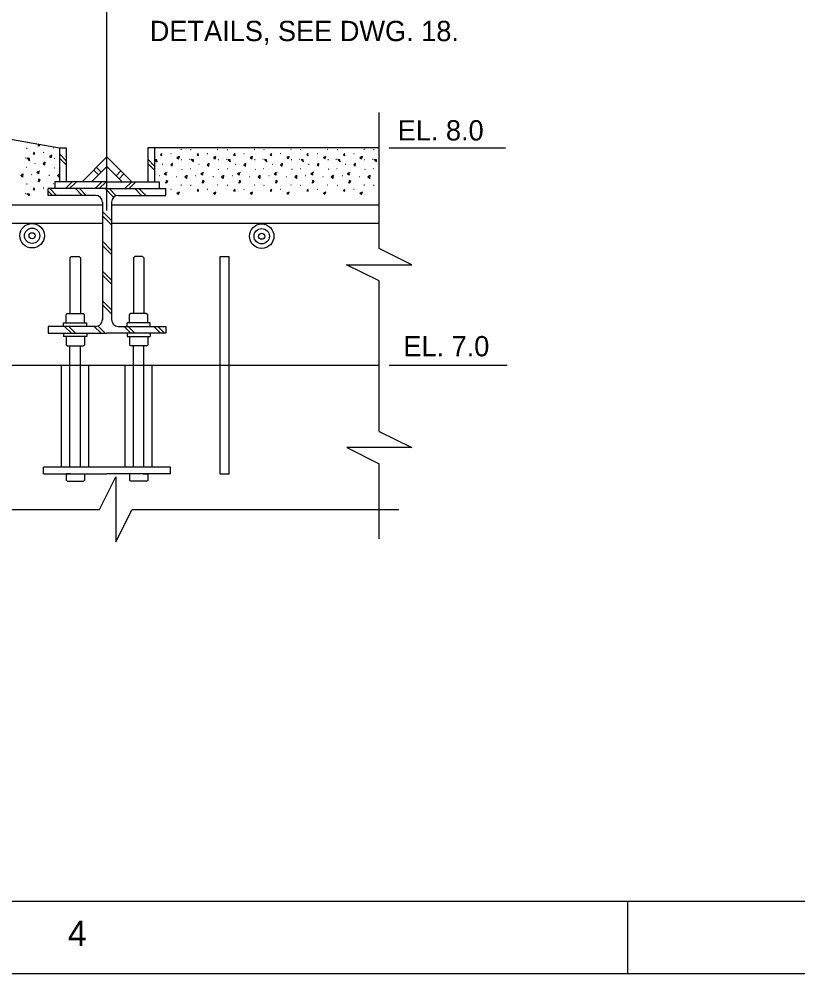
# Model space of a CAD drawing. Extents: x 0 to 320, y -4 to 473.
# Drawn here: x 12.43 to 17.8, y 0 to 6.59 of the extents above; entities that cross this region are included whole.
import ezdxf

# ---------------------------------------------------------------- set-up
doc = ezdxf.new("R2010")
doc.units = 0
for name, color, linetype in [('Level 1', 7, 'Continuous'), ('Level 2', 7, 'Continuous'), ('Level 44', 7, 'Continuous'), ('Level 50', 7, 'Continuous')]:
    doc.layers.add(name, color=color, linetype=linetype)

msp = doc.modelspace()

# ---------------------------------------------------------------- linework, layer by layer
at = {"layer": 'Level 1'}
msp.add_line((16.625, 0.5), (16.625, 0), dxfattribs=at)
for points in [[(0, 28), (40, 28), (40, 0), (0, 0)], [(1.5, 27.5), (39.5, 27.5), (39.5, 0.5), (1.5, 0.5)]]:
    msp.add_lwpolyline(points, close=True, dxfattribs=at)
at = {"layer": 'Level 2'}
for p, q in [((12.0104, 5.8276), (12.7057, 5.7025)), ((12.7057, 5.7025), (12.7057, 5.4682)), ((12.7057, 5.7025), (12.7526, 5.7025)), ((12.7526, 5.7025), (12.7526, 5.4682)), ((14.9124, 5.7025), (13.3151, 5.7025)), ((13.3151, 5.7025), (13.3151, 5.4682)), ((13.3619, 5.7025), (13.3619, 5.4682)), ((12.7526, 5.6139), (12.7057, 5.6608)), ((12.7526, 5.5856), (12.7057, 5.6325)), ((13.0338, 5.64), (12.8619, 5.4682)), ((13.0338, 5.64), (13.2057, 5.4682)), ((13.3619, 5.577), (13.3151, 5.6238)), ((13.0338, 5.5738), (12.9282, 5.4682)), ((12.9759, 5.5159), (12.9428, 5.549)), ((12.9949, 5.5348), (12.9618, 5.568)), ((13.0338, 5.5738), (13.1394, 5.4682)), ((13.0971, 5.5104), (13.1303, 5.5436)), ((13.3619, 5.5487), (13.3151, 5.5956)), ((13.1174, 5.4902), (13.1505, 5.5233)), ((13.0338, 5.4213), (12.6276, 5.4213)), ((12.6276, 5.3744), (12.6276, 5.4213)), ((12.6859, 5.3744), (12.639, 5.4213)), ((13.0338, 5.4682), (12.6744, 5.4682)), ((12.6744, 5.4682), (12.6744, 5.4213)), ((12.7476, 5.4213), (12.7945, 5.4682)), ((12.7759, 5.4213), (12.8227, 5.4682)), ((12.8627, 5.3744), (12.8158, 5.4213)), ((12.8909, 5.3744), (12.8441, 5.4213)), ((12.9526, 5.4213), (12.9995, 5.4682)), ((12.9809, 5.4213), (13.0278, 5.4682)), ((13.0801, 5.362), (13.0209, 5.4213)), ((13.0338, 5.4682), (13.3932, 5.4682)), ((13.0338, 5.4213), (13.4401, 5.4213)), ((13.0981, 5.3723), (13.0491, 5.4213)), ((13.1577, 5.4213), (13.2046, 5.4682)), ((13.186, 5.4213), (13.2329, 5.4682)), ((13.2728, 5.3744), (13.2259, 5.4213)), ((13.3011, 5.3744), (13.2542, 5.4213)), ((13.3932, 5.4682), (13.3932, 5.4213)), ((13.4401, 5.3744), (13.4401, 5.4213)), ((12.6576, 5.3744), (12.6276, 5.4045)), ((12.9557, 5.3744), (12.6276, 5.3744)), ((13.1119, 5.3744), (13.4401, 5.3744)), ((13.0026, 5.3068), (11.4791, 5.3068)), ((13.0026, 5.3275), (13.0026, 4.5135)), ((13.0651, 5.3275), (13.0651, 4.5135)), ((14.9124, 5.3068), (13.0651, 5.3068)), ((13.0651, 5.2003), (13.0026, 5.2628)), ((13.0651, 5.172), (13.0026, 5.2345)), ((13.0026, 5.1818), (11.4791, 5.1818)), ((14.9124, 5.1818), (13.0651, 5.1818)), ((13.0651, 4.9953), (13.0026, 5.0578)), ((13.0651, 4.967), (13.0026, 5.0295)), ((12.7785, 4.9434), (12.7876, 4.9525)), ((12.7876, 4.9525), (12.8421, 4.9525)), ((12.8512, 4.9434), (12.8421, 4.9525)), ((13.2164, 4.9434), (13.2255, 4.9525)), ((13.28, 4.9525), (13.2255, 4.9525)), ((13.2891, 4.9434), (13.28, 4.9525)), ((13.8151, 3.4525), (13.8151, 4.9525)), ((13.8776, 3.4525), (13.8776, 4.9525)), ((12.7787, 4.9434), (12.7787, 4.5583)), ((12.8514, 4.9434), (12.8514, 4.5583)), ((13.2162, 4.9434), (13.2162, 4.5583)), ((13.2889, 4.9434), (13.2889, 4.5583)), ((13.0651, 4.7902), (13.0026, 4.8527)), ((13.0651, 4.7619), (13.0026, 4.8244)), ((13.0651, 4.5851), (13.0026, 4.6476)), ((13.0651, 4.5568), (13.0026, 4.6193)), ((12.7607, 4.5583), (12.7523, 4.5534)), ((12.7523, 4.4938), (12.7523, 4.5534)), ((12.7607, 4.5583), (12.8694, 4.5583)), ((12.8694, 4.5583), (12.8779, 4.5534)), ((12.8779, 4.4938), (12.8779, 4.5534)), ((13.1982, 4.5583), (13.1898, 4.5534)), ((13.1898, 4.4938), (13.1898, 4.5534)), ((13.3069, 4.5583), (13.1982, 4.5583)), ((13.3069, 4.5583), (13.3154, 4.5534)), ((13.3154, 4.4938), (13.3154, 4.5534)), ((12.7348, 4.4938), (12.8954, 4.4938)), ((12.7348, 4.4703), (12.7348, 4.4938)), ((12.7787, 4.4915), (12.7787, 4.4938)), ((12.8514, 4.4915), (12.8514, 4.4938)), ((12.8954, 4.4703), (12.8954, 4.4938)), ((13.3329, 4.4938), (13.1723, 4.4938)), ((13.1723, 4.4703), (13.1723, 4.4938)), ((13.2162, 4.4915), (13.2162, 4.4938)), ((13.2889, 4.4915), (13.2889, 4.4938)), ((13.3329, 4.4703), (13.3329, 4.4938)), ((12.9557, 4.4703), (12.6276, 4.4703)), ((12.6276, 4.4703), (12.6276, 4.4235)), ((12.6276, 4.4235), (13.0338, 4.4235)), ((12.7348, 4.4235), (12.7348, 4.4)), ((12.7883, 4.4235), (12.7414, 4.4703)), ((12.8166, 4.4235), (12.7697, 4.4703)), ((12.8954, 4.4235), (12.8954, 4.4)), ((12.9934, 4.4235), (12.9465, 4.4703)), ((13.0216, 4.4235), (12.9719, 4.4732)), ((13.4401, 4.4235), (13.0338, 4.4235)), ((13.1119, 4.4703), (13.4401, 4.4703)), ((13.1984, 4.4235), (13.1516, 4.4703)), ((13.1723, 4.4235), (13.1723, 4.4)), ((13.2267, 4.4235), (13.1798, 4.4703)), ((13.3329, 4.4235), (13.3329, 4.4)), ((13.4035, 4.4235), (13.3566, 4.4703)), ((13.4318, 4.4235), (13.3849, 4.4703)), ((13.4401, 4.4703), (13.4401, 4.4235)), ((12.8954, 4.4), (12.7348, 4.4)), ((12.7523, 4.4), (12.7523, 4.3404)), ((12.7787, 4.4023), (12.7787, 4.4)), ((12.8514, 4.4023), (12.8514, 4.4)), ((12.8779, 4.4), (12.8779, 4.3404)), ((13.1723, 4.4), (13.3329, 4.4)), ((13.1898, 4.4), (13.1898, 4.3404)), ((13.2162, 4.4023), (13.2162, 4.4)), ((13.2889, 4.4023), (13.2889, 4.4)), ((13.3154, 4.4), (13.3154, 4.3404)), ((12.7607, 4.3355), (12.7523, 4.3404)), ((12.7607, 4.3355), (12.8694, 4.3355)), ((12.7787, 3.4994), (12.7787, 4.3355)), ((12.8514, 3.4994), (12.8514, 4.3355)), ((12.8694, 4.3355), (12.8779, 4.3404)), ((13.1982, 4.3355), (13.1898, 4.3404)), ((13.3069, 4.3355), (13.1982, 4.3355)), ((13.2162, 3.4994), (13.2162, 4.3355)), ((13.2889, 3.4994), (13.2889, 4.3355)), ((13.3069, 4.3355), (13.3154, 4.3404)), ((7.5674, 4.2025), (14.9124, 4.2025)), ((12.7213, 3.4994), (12.7213, 4.2025)), ((12.9088, 3.4994), (12.9088, 4.2025)), ((13.1588, 3.4994), (13.1588, 4.2025)), ((13.3463, 3.4994), (13.3463, 4.2025)), ((12.5963, 3.4525), (12.5963, 3.4994)), ((13.0338, 3.4994), (12.5963, 3.4994)), ((13.4713, 3.4994), (13.0338, 3.4994)), ((13.4713, 3.4525), (13.4713, 3.4994)), ((12.5963, 3.4525), (13.0338, 3.4525)), ((12.7844, 3.4523), (12.7526, 3.4523)), ((12.7526, 3.4523), (12.7526, 3.4063)), ((12.779, 3.4546), (12.779, 3.4523)), ((12.8518, 3.4546), (12.8518, 3.4523)), ((12.8782, 3.4523), (12.8782, 3.4063)), ((13.4713, 3.4525), (13.0338, 3.4525)), ((13.1894, 3.4523), (13.1894, 3.4063)), ((13.2158, 3.4546), (13.2158, 3.4523)), ((13.2832, 3.4523), (13.315, 3.4523)), ((13.2886, 3.4546), (13.2886, 3.4523)), ((13.315, 3.4523), (13.315, 3.4063)), ((12.761, 3.4014), (12.7526, 3.4063)), ((12.761, 3.4014), (12.8698, 3.4014)), ((12.8698, 3.4014), (12.8782, 3.4063)), ((13.1978, 3.4014), (13.1894, 3.4063)), ((13.3066, 3.4014), (13.1978, 3.4014)), ((13.3066, 3.4014), (13.315, 3.4063))]:
    msp.add_line(p, q, dxfattribs=at)
for centre, start, end in [((12.9557, 5.3275), 0.00001, 90), ((13.1119, 5.3275), 90, 179.99999), ((12.9557, 4.5172), 269.99999, 359.99999), ((13.1119, 4.5172), 180.00001, 270)]:
    msp.add_arc(centre, 0.0469, start, end, dxfattribs=at)
at = {"layer": 'Level 44'}
for p, q in [((14.9124, 5.0084), (14.9124, 5.9461)), ((12.4828, 5.6984), (12.4794, 5.6984)), ((12.5597, 5.7152), (12.5572, 5.7154)), ((12.5973, 5.6711), (12.5943, 5.6696)), ((12.6681, 5.7005), (12.6656, 5.701)), ((13.5471, 5.6918), (13.5446, 5.6923)), ((13.6144, 5.6897), (13.611, 5.6897)), ((13.7996, 5.6918), (13.7971, 5.6923)), ((13.8669, 5.6897), (13.8635, 5.6897)), ((14.0521, 5.6918), (14.0496, 5.6923)), ((14.1194, 5.6897), (14.116, 5.6897)), ((14.3046, 5.6918), (14.3021, 5.6923)), ((14.3719, 5.6897), (14.3685, 5.6897)), ((14.5571, 5.6918), (14.5546, 5.6923)), ((14.6244, 5.6897), (14.621, 5.6897)), ((14.8096, 5.6918), (14.8071, 5.6923)), ((14.8769, 5.6897), (14.8735, 5.6897)), ((14.9812, 5.7025), (15.7839, 5.7025)), ((12.4756, 5.6308), (12.4724, 5.6308)), ((12.6721, 5.6296), (12.6687, 5.6296)), ((13.4764, 5.6624), (13.4734, 5.6609)), ((13.5511, 5.6209), (13.5477, 5.6209)), ((13.6071, 5.6221), (13.6039, 5.6221)), ((13.7289, 5.6624), (13.7259, 5.6609)), ((13.8036, 5.6209), (13.8002, 5.6209)), ((13.8596, 5.6221), (13.8564, 5.6221)), ((13.9814, 5.6624), (13.9784, 5.6609)), ((14.0561, 5.6209), (14.0527, 5.6209)), ((14.1121, 5.6221), (14.1089, 5.6221)), ((14.2339, 5.6624), (14.2309, 5.6609)), ((14.3086, 5.6209), (14.3052, 5.6209)), ((14.3646, 5.6221), (14.3614, 5.6221)), ((14.4864, 5.6624), (14.4834, 5.6609)), ((14.5611, 5.6209), (14.5577, 5.6209)), ((14.6171, 5.6221), (14.6139, 5.6221)), ((14.7389, 5.6624), (14.7359, 5.6609)), ((14.8136, 5.6209), (14.8102, 5.6209)), ((14.8696, 5.6221), (14.8664, 5.6221)), ((12.4805, 5.5675), (12.4781, 5.5666)), ((12.5392, 5.5959), (12.5359, 5.5964)), ((12.571, 5.541), (12.5682, 5.5427)), ((12.6747, 5.5642), (12.6714, 5.5632)), ((13.4182, 5.5871), (13.415, 5.5877)), ((13.5538, 5.5555), (13.5504, 5.5545)), ((13.612, 5.5588), (13.6096, 5.5579)), ((13.6707, 5.5871), (13.6675, 5.5877)), ((13.8063, 5.5555), (13.8029, 5.5545)), ((13.8645, 5.5588), (13.8621, 5.5579)), ((13.9232, 5.5871), (13.92, 5.5877)), ((14.0588, 5.5555), (14.0554, 5.5545)), ((14.117, 5.5588), (14.1146, 5.5579)), ((14.1757, 5.5871), (14.1725, 5.5877)), ((14.3113, 5.5555), (14.3079, 5.5545)), ((14.3695, 5.5588), (14.3671, 5.5579)), ((14.4282, 5.5871), (14.425, 5.5877)), ((14.5638, 5.5555), (14.5604, 5.5545)), ((14.622, 5.5588), (14.6196, 5.5579)), ((14.6807, 5.5871), (14.6775, 5.5877)), ((14.8163, 5.5555), (14.8129, 5.5545)), ((14.8745, 5.5588), (14.8721, 5.5579)), ((12.5166, 5.5178), (12.5139, 5.519)), ((12.6365, 5.5118), (12.6337, 5.5115)), ((13.3956, 5.5091), (13.3929, 5.5103)), ((13.45, 5.5323), (13.4472, 5.534)), ((13.5155, 5.5031), (13.5128, 5.5028)), ((13.6481, 5.5091), (13.6454, 5.5103)), ((13.7025, 5.5323), (13.6997, 5.534)), ((13.768, 5.5031), (13.7653, 5.5028)), ((13.9006, 5.5091), (13.8979, 5.5103)), ((13.955, 5.5323), (13.9522, 5.534)), ((14.0205, 5.5031), (14.0178, 5.5028)), ((14.1531, 5.5091), (14.1504, 5.5103)), ((14.2075, 5.5323), (14.2047, 5.534)), ((14.273, 5.5031), (14.2703, 5.5028)), ((14.4056, 5.5091), (14.4029, 5.5103)), ((14.46, 5.5323), (14.4572, 5.534)), ((14.5255, 5.5031), (14.5228, 5.5028)), ((14.6581, 5.5091), (14.6554, 5.5103)), ((14.7125, 5.5323), (14.7097, 5.534)), ((14.778, 5.5031), (14.7753, 5.5028)), ((14.9106, 5.5091), (14.9079, 5.5103)), ((12.4828, 5.4525), (12.4794, 5.4525)), ((12.5597, 5.4692), (12.5572, 5.4694)), ((12.5973, 5.4252), (12.5943, 5.4237)), ((12.6681, 5.4546), (12.6656, 5.455)), ((13.4388, 5.4605), (13.4363, 5.4607)), ((13.4764, 5.4165), (13.4734, 5.415)), ((13.5471, 5.4459), (13.5446, 5.4463)), ((13.6144, 5.4438), (13.611, 5.4438)), ((13.6913, 5.4605), (13.6888, 5.4607)), ((13.7289, 5.4165), (13.7259, 5.415)), ((13.7996, 5.4459), (13.7971, 5.4463)), ((13.8669, 5.4438), (13.8635, 5.4438)), ((13.9438, 5.4605), (13.9413, 5.4607)), ((13.9814, 5.4165), (13.9784, 5.415)), ((14.0521, 5.4459), (14.0496, 5.4463)), ((14.1194, 5.4438), (14.116, 5.4438)), ((14.1963, 5.4605), (14.1938, 5.4607)), ((14.2339, 5.4165), (14.2309, 5.415)), ((14.3046, 5.4459), (14.3021, 5.4463)), ((14.3719, 5.4438), (14.3685, 5.4438)), ((14.4488, 5.4605), (14.4463, 5.4607)), ((14.4864, 5.4165), (14.4834, 5.415)), ((14.5571, 5.4459), (14.5546, 5.4463)), ((14.6244, 5.4438), (14.621, 5.4438)), ((14.7013, 5.4605), (14.6988, 5.4607)), ((14.7389, 5.4165), (14.7359, 5.415)), ((14.8096, 5.4459), (14.8071, 5.4463)), ((14.8769, 5.4438), (14.8735, 5.4438)), ((12.4756, 5.3849), (12.4724, 5.3849)), ((13.8151, 4.9525), (13.8776, 4.9525)), ((14.9124, 3.7449), (14.9124, 4.7841)), ((14.9812, 4.2025), (15.7937, 4.2025)), ((14.9124, 3.0027), (14.9124, 3.5207)), ((13.8151, 3.4525), (13.8776, 3.4525)), ((10.9819, 3.2068), (12.9835, 3.2068)), ((13.2077, 3.2068), (15.0473, 3.2068))]:
    msp.add_line(p, q, dxfattribs=at)
for points in [[(12.4516, 5.7467), (12.4495, 5.7486)], [(12.4516, 5.7482), (12.4516, 5.7467)], [(12.5624, 5.7283), (12.5634, 5.7143)], [(12.5634, 5.7143), (12.574, 5.7262)], [(13.378, 5.6213), (13.3646, 5.622)], [(13.3646, 5.6205), (13.3793, 5.6055), (13.378, 5.6213)], [(12.499, 5.384), (12.484, 5.3849), (12.4945, 5.3741)], [(12.4998, 5.3741), (12.499, 5.384)]]:
    msp.add_lwpolyline(points, dxfattribs=at)
for points in [[(12.5333, 5.6584), (12.5316, 5.6721), (12.5239, 5.6607)], [(12.499, 5.63), (12.484, 5.6308), (12.5002, 5.6142)], [(12.6074, 5.6049), (12.5946, 5.5937), (12.6052, 5.5847)], [(12.6484, 5.6369), (12.6544, 5.6522), (12.6378, 5.6442)], [(13.4124, 5.6497), (13.4106, 5.6634), (13.4029, 5.652)], [(13.5275, 5.6282), (13.5334, 5.6435), (13.5169, 5.6355)], [(13.6305, 5.6213), (13.6155, 5.6221), (13.6318, 5.6055)], [(13.6649, 5.6497), (13.6631, 5.6634), (13.6554, 5.652)], [(13.78, 5.6282), (13.7859, 5.6435), (13.7694, 5.6355)], [(13.883, 5.6213), (13.868, 5.6221), (13.8843, 5.6055)], [(13.9174, 5.6497), (13.9156, 5.6634), (13.9079, 5.652)], [(14.0325, 5.6282), (14.0384, 5.6435), (14.0219, 5.6355)], [(14.1355, 5.6213), (14.1205, 5.6221), (14.1368, 5.6055)], [(14.1699, 5.6497), (14.1681, 5.6634), (14.1604, 5.652)], [(14.285, 5.6282), (14.2909, 5.6435), (14.2744, 5.6355)], [(14.388, 5.6213), (14.373, 5.6221), (14.3893, 5.6055)], [(14.4224, 5.6497), (14.4206, 5.6634), (14.4129, 5.652)], [(14.5375, 5.6282), (14.5434, 5.6435), (14.5269, 5.6355)], [(14.6405, 5.6213), (14.6255, 5.6221), (14.6418, 5.6055)], [(14.6749, 5.6497), (14.6731, 5.6634), (14.6654, 5.652)], [(14.79, 5.6282), (14.7959, 5.6435), (14.7794, 5.6355)], [(14.893, 5.6213), (14.878, 5.6221), (14.8943, 5.6055)], [(12.5621, 5.5234), (12.5501, 5.5324), (12.5616, 5.5426)], [(13.4865, 5.5961), (13.4737, 5.585), (13.4843, 5.576)], [(13.739, 5.5961), (13.7262, 5.585), (13.7368, 5.576)], [(13.9915, 5.5961), (13.9787, 5.585), (13.9893, 5.576)], [(14.244, 5.5961), (14.2312, 5.585), (14.2418, 5.576)], [(14.4965, 5.5961), (14.4837, 5.585), (14.4943, 5.576)], [(14.749, 5.5961), (14.7362, 5.585), (14.7468, 5.576)], [(12.4516, 5.5008), (12.44, 5.5115), (12.4528, 5.5229)], [(12.5634, 5.4684), (12.5741, 5.4804), (12.5621, 5.4867)], [(12.7041, 5.5008), (12.6925, 5.5115), (12.7053, 5.5229)], [(13.4412, 5.5146), (13.4292, 5.5237), (13.4407, 5.5339)], [(13.4424, 5.4596), (13.4531, 5.4716), (13.4412, 5.478)], [(13.5831, 5.4921), (13.5715, 5.5028), (13.5844, 5.5142)], [(13.6937, 5.5146), (13.6817, 5.5237), (13.6932, 5.5339)], [(13.6949, 5.4596), (13.7056, 5.4716), (13.6937, 5.478)], [(13.8356, 5.4921), (13.824, 5.5028), (13.8369, 5.5142)], [(13.9462, 5.5146), (13.9342, 5.5237), (13.9457, 5.5339)], [(13.9474, 5.4596), (13.9581, 5.4716), (13.9462, 5.478)], [(14.0881, 5.4921), (14.0765, 5.5028), (14.0894, 5.5142)], [(14.1987, 5.5146), (14.1867, 5.5237), (14.1982, 5.5339)], [(14.1999, 5.4596), (14.2106, 5.4716), (14.1987, 5.478)], [(14.3406, 5.4921), (14.329, 5.5028), (14.3419, 5.5142)], [(14.4512, 5.5146), (14.4392, 5.5237), (14.4507, 5.5339)], [(14.4524, 5.4596), (14.4631, 5.4716), (14.4512, 5.478)], [(14.5931, 5.4921), (14.5815, 5.5028), (14.5944, 5.5142)], [(14.7037, 5.5146), (14.6917, 5.5237), (14.7032, 5.5339)], [(14.7049, 5.4596), (14.7156, 5.4716), (14.7037, 5.478)], [(14.8456, 5.4921), (14.834, 5.5028), (14.8469, 5.5142)], [(12.5333, 5.4125), (12.5316, 5.4262), (12.5239, 5.4147)], [(13.6649, 5.4038), (13.6631, 5.4175), (13.6554, 5.406)], [(13.9174, 5.4038), (13.9156, 5.4175), (13.9079, 5.406)], [(14.1699, 5.4038), (14.1681, 5.4175), (14.1604, 5.406)], [(14.4224, 5.4038), (14.4206, 5.4175), (14.4129, 5.406)], [(14.6749, 5.4038), (14.6731, 5.4175), (14.6654, 5.406)], [(13.5275, 5.3823), (13.5334, 5.3976), (13.5169, 5.3895)], [(13.78, 5.3823), (13.7859, 5.3976), (13.7694, 5.3895)], [(14.0325, 5.3823), (14.0384, 5.3976), (14.0219, 5.3895)], [(14.285, 5.3823), (14.2909, 5.3976), (14.2744, 5.3895)], [(14.5375, 5.3823), (14.5434, 5.3976), (14.5269, 5.3895)], [(14.79, 5.3823), (14.7959, 5.3976), (14.7794, 5.3895)]]:
    msp.add_lwpolyline(points, close=True, dxfattribs=at)
at = {"layer": 'Level 50'}
for p, q in [((13.0338, 5.2705), (13.0338, 7.4143)), ((15.1369, 4.8959), (14.9124, 5.0084)), ((14.9124, 4.7841), (14.6874, 4.8959)), ((14.6874, 4.8959), (15.1369, 4.8959)), ((14.9124, 3.7449), (15.1374, 3.6332)), ((15.1374, 3.6332), (14.6879, 3.6332)), ((14.6879, 3.6332), (14.9124, 3.5207)), ((12.9835, 3.2068), (13.0952, 3.4318)), ((13.0952, 3.4318), (13.0952, 2.9823)), ((13.0952, 2.9823), (13.2077, 3.2068))]:
    msp.add_line(p, q, dxfattribs=at)
for centre, radius in [((12.5177, 5.0961), 0.0844), ((12.5177, 5.0961), 0.0527), ((14.1014, 5.0931), 0.0844), ((14.1014, 5.0931), 0.0527), ((12.5177, 5.0961), 0.0211), ((14.1014, 5.0931), 0.0211)]:
    msp.add_circle(centre, radius, dxfattribs=at)

# ---------------------------------------------------------------- texts
at = {"layer": 'Level 1'}
msp.add_text('4', height=0.1753, dxfattribs=at).set_placement((12.7634, 0.1919))
at = {"layer": 'Level 50'}
for s, height, p in [('DETAILS, SEE DWG. 18.', 0.140021, (13.3291, 6.4399)), ('EL. 8.0', 0.14002, (15.0393, 5.7539)), ('EL. 7.0', 0.14002, (15.0784, 4.2637))]:
    msp.add_text(s, height=height, dxfattribs=at).set_placement(p)

doc.saveas('drawing.dxf')
